(* Logix 5000 project; controller PDPMV1_60_v16 vendor 1 type 14 code 65 rev 16.20; software revision 16.03 *)
// MVI69-PDPMV1

TASK MainTask (continuous, watchdog 500 ms) : MainProgram

MODULES
   Controller : vendor 1 type 14 code 65 (CompactLogixL35Controller 0, rev 16.20)
      LocalENB : 1769-L35E Ethernet Port (CompactLogixL35Ethernet 1, rev 16.3)
      Local : CompactBus (CompactVirtualAdapter 3, rev 16.3, Input RPI 5 ms)
         PDPMV1_60 : 1769-MODULE (Compact 1, rev 1.1, Output RPI 2 ms)
END_MODULES

TYPE PDPMV1_AbortConnection :
STRUCT
   Out : PDPMV1_AbortConnection_out;   // Mailbox Request
   In : PDPMV1_AbortConnection_In;   // Mailbox Response
END_STRUCT
END_TYPE

TYPE PDPMV1_AbortConnection_In :
STRUCT
   C_REF : INT;   // Connection reference that shall be terminated.
   ReasonCode : SINT;   // Indicates the reason for the abort request. Value is user-specific. Range 0...15
   Subnet : SINT;   // This parameter encodes information about the origin of the abort initiator. 0: No 1: Local 2: Remote 3...255: (reserved)
   ExtendedFaultInformation : INT;   // If ‘Fault Information’ equals 000Ah or 000Bh, additional information of the error can be found here. For more information,
   FaultInformation : INT;   // If ‘Invalid Other’ is returned in the Message Information word in the header of the response,
END_STRUCT
END_TYPE

TYPE PDPMV1_AbortConnection_out :
STRUCT
   C_REF : INT;   // Connection reference that shall be terminated
   ReasonCode : SINT;   // Indicates the reason for the abort request. Value is user-specific. Range 0...15.
   Subnet : SINT;   // This parameter encodes information about the origin of the abort initiator. 0: No 1: Local 2: Remote
END_STRUCT
END_TYPE

TYPE PDPMV1_Alarm :   // DPV1 alarm data received by the module
STRUCT
   ByteCount : INT;   // Byte count data block
   SlotNumber : SINT;   // Used in the slave to address the desired data block. Range 0-254
   SlaveAddress : SINT;   // Destination of slave (1-125)
   AlarmSpecAck : SINT;   // Additional alarm information
   SeqNumber : SINT;   // Unique ID number of the alarm. Range 0-31.
   ExtDiag : SINT;   // Extended Diagnostic Flag (FFh - flag set and 00h - flag cleared).
   AlarmType : SINT;   // Identifies alarm type. Range is from 1 to 6, 32 to 126.
   FaultInformation : SINT;   // If other than 0, refer to user manual for code information
   Data : SINT[500];   // Returned data [1...n] array with additional manf. spec alarm info.
END_STRUCT
END_TYPE

TYPE PDPMV1_backplane :   // This object stores variables used by the sample ladder for handshaking.
STRUCT
   Read : INT;   // Backplane read statistics
   Write : INT;   // Backplane write statistics
   Error : INT;   // Backplane error statistics
   LastRead : INT;   // Last read block index received from the module
   LastWrite : INT;   // Last write block index received from the module
   BlockIndex : INT;   // Block index of each copy of PROFIBUS input and output blocks
END_STRUCT
END_TYPE

TYPE PDPMV1_backplane2 :   // This object stores variables used by the sample ladder for handshaking.
STRUCT
   LastRead : INT;   // Last read block index received from the module
   LastWrite : INT;   // Last write block index received from the module
   BlockIndex : INT;   // Block index of each copy of PROFIBUS input and output blocks
END_STRUCT
END_TYPE

TYPE PDPMV1_Class1AcyclicRead :   // DPV1 acyclic read mailbox data structure
STRUCT
   Out : PDPMV1_Class1AcyclicRead_Out;   // Mailbox request
   In : PDPMV1_Class1AcyclicRead_In;   // Mailbox response
END_STRUCT
END_TYPE

TYPE PDPMV1_Class1AcyclicRead_In :   // DPV1 acyclic read mailbox response
STRUCT
   ByteCount : INT;   // Byte count data block
   SlotNumber : SINT;   // Used in the slave to address the desired data block.
   SlaveAddress : SINT;   // Destination of slave (1-125)
   Length : SINT;   // Specifies the number of bytes of the data block to read
   Index : SINT;   // Index block
   ErrorDecode : SINT;   // If other than 0, refer to user manual for code information
   ErrorCode2 : SINT;   // If other than 0, refer to user manual for code information
   ErrorCode1 : SINT;   // If other than 0, refer to user manual for code information
   ExtendedFaultInfo : SINT;   // If other than 0, refer to user manual for code information
   FaultInformation : SINT;   // If other than 0, refer to user manual for code information
   Data : SINT[300];   // Returned data [1...n] array
END_STRUCT
END_TYPE

TYPE PDPMV1_Class1AcyclicRead_Out :   // DPV1 acyclic read mailbox request
STRUCT
   SlotNumber : SINT;   // Used in the slave to address the desired data block.
   SlaveAddress : SINT;   // Destination of slave (1-125)
   DataSize : INT;   // Object data size
   Length : SINT;   // Specifies the number of bytes of the data block to read
   Index : SINT;   // Index block
END_STRUCT
END_TYPE

TYPE PDPMV1_Class1AcyclicWrite :   // DPV1 acyclic write mailbox data structure
STRUCT
   Out : PDPMV1_Class1AcyclicWrite_Out;   // Mailbox request
   In : PDPMV1_Class1AcyclicWrite_In;   // Mailbox response
END_STRUCT
END_TYPE

TYPE PDPMV1_Class1AcyclicWrite_In :   // DPV1 acyclic write mailbox response
STRUCT
   ByteCount : INT;   // Byte count data block
   SlotNumber : SINT;   // Used in the slave to address the desired data block.
   SlaveAddress : SINT;   // Destination of slave (1-125)
   Length : SINT;   // Specifies the number of bytes of the data block to read
   Index : SINT;   // Index block
   ErrorDecode : SINT;   // If other than 0, refer to user manual for code information
   ErrorCode2 : SINT;   // If other than 0, refer to user manual for code information
   ErrorCode1 : SINT;   // If other than 0, refer to user manual for code information
   ExtendedFaultInfo : INT;   // If other than 0, refer to user manual for code information
   FaultInformation : INT;   // If other than 0, refer to user manual for code information
   Data : SINT[300];   // Returned data [1...n] array
END_STRUCT
END_TYPE

TYPE PDPMV1_Class1AcyclicWrite_Out :   // DPV1 acyclic write mailbox request
STRUCT
   SlotNumber : SINT;   // Used in the slave to address the desired data block.
   SlaveAddress : SINT;   // Destination of slave (1-125)
   DataSize : INT;   // Object data size
   Length : SINT;   // Specifies the number of bytes of the data block to read
   Index : SINT;   // Index Block
   Data : SINT[300];   // Data that should be written [1...n]
END_STRUCT
END_TYPE

TYPE PDPMV1_Class2AcyclicRead :
STRUCT
   Out : PDPMV1_Class2AcyclicRead_Out;   // Mailbox request
   In : PDPMV1_Class2AcyclicRead_In;   // Mailbox response
END_STRUCT
END_TYPE

TYPE PDPMV1_Class2AcyclicRead_In :
STRUCT
   DataSize : INT;   // Byte count data block
   C_REF : INT;   // Connections references used to identify the connection later on. Range: 1-128
   Index : SINT;   // Index block
   SlotNumber : SINT;   // Used in the slave to address the desired data block.
   Length : INT;   // Specifies the number of bytes of the data block to read
   ErrorDecode : INT;   // If other than 0, refer to user manual for code information
   ErrorCode2 : SINT;   // If other than 0, refer to user manual for code information
   ErrorCode1 : SINT;   // If other than 0, refer to user manual for code information
   ExtendedFaultInfo : SINT;   // If other than 0, refer to user manual for code information
   FaultInformation : SINT;   // If other than 0, refer to user manual for code information
   Data : SINT[244];   // Returned data [1...n] array
END_STRUCT
END_TYPE

TYPE PDPMV1_Class2AcyclicRead_Out :
STRUCT
   C_REF : INT;   // Connection reference that shall be terminated
   Index : SINT;   // Used in the slave for addressing of the desired data block. Range 0...254
   SlotNumber : SINT;   // Used in the slave for addressing of the desired data block. Range 0...254
   Length : INT;   // Number of bytes to write
END_STRUCT
END_TYPE

TYPE PDPMV1_Class2AcyclicWrite :   // DPV1 acyclic write mailbox data structure
STRUCT
   Out : PDPMV1_Class2AcyclicWrite_Out;   // Mailbox request
   In : PDPMV1_Class2AcyclicWrite_In;   // Mailbox response
END_STRUCT
END_TYPE

TYPE PDPMV1_Class2AcyclicWrite_In :   // DPV1 acyclic write mailbox response
STRUCT
   ByteCount : INT;   // Byte count data block
   C_REF : INT;   // Connection reference that shall be Read
   Index : SINT;   // Index block
   SlotNumber : SINT;   // Used in the slave to address the desired data block.
   Length : SINT;   // Specifies the number of bytes of the data block to read
   ErrorDecode : SINT;   // If other than 0, refer to user manual for code information
   ErrorCode2 : SINT;   // If other than 0, refer to user manual for code information
   ErrorCode1 : SINT;   // If other than 0, refer to user manual for code information
   ExtendedFaultInfo : SINT;   // If other than 0, refer to user manual for code information
   FaultInformation : SINT;   // If other than 0, refer to user manual for code information
   Data : SINT[244];   // Returned data [1...n] array
END_STRUCT
END_TYPE

TYPE PDPMV1_Class2AcyclicWrite_Out :   // DPV1 acyclic write mailbox request
STRUCT
   DataSize : INT;   // Object data size
   C_REF : INT;   // Connection reference that shall be terminated
   Index : SINT;   // Index block
   SlotNumber : SINT;   // Used in the slave to address the desired data block.
   Length : INT;   // Specifies the number of bytes of the data block to read
   Data : SINT[244];   // Data that should be written [1...n]
END_STRUCT
END_TYPE

TYPE PDPMV1_Command :   // This object contains the command bits that request mailbox messages from the module.
STRUCT
   StopMode : BOOL;   // Set the module to stop mode (PROFIBUS communication is interrupted in stop mode)
   OperateMode : BOOL;   // Set the module to operate mode (module only communicates through PROFIBUS)
   ClearMode : BOOL;   // Set the module to clear mode (outputs are disabled)
   SynchCRC : BOOL;   // CRC synchronization
   GetLiveList : BOOL;   // Request the Live List information from the module
   GetSlaveConfig : BOOL;   // Request configuration information from slave
   SetSlaveMode : BOOL;   // Set the module to stop mode (PROFIBUS communication is interrupted in stop mode)
   GetSlaveDiagnostics : BOOL;   // Requests slave diagnostics from a slave
   SetSlaveAddress : BOOL;   // Change the slave's PROFIBUS address 100 (only if slave supports this feature)
   StartSlaves : BOOL;   // Restarts PROFIBUS communication with one or more slaves after a "StopSlave" mailbox
   StopSlaves : BOOL;   // Stop PROFIBUS communication with one or more slaves
   Class1AcyclicRead : BOOL;   // Request the module to send acyclic read message to slave
   Class1AcyclicWrite : BOOL;   // Request the module to send acyclic write message to the slave
   InitiateConnection : BOOL;   // Request to establish connection with a V1 slave that can handle class 2 messages
   AbortConnection : BOOL;   // Request to Abort an already established connection with a V1 slave that can handle class 2 messages
   Class2AcyclicRead : BOOL;   // Request the module to send class 2 acyclic Read message to a V1 slave
   Class2AcyclicWrite : BOOL;   // Request the module to send class 2 acyclic Write message to a V1 slave
END_STRUCT
END_TYPE

TYPE PDPMV1_Control :   // Control status
STRUCT
   serial_number : SINT[4];   // Module serial number
   version_MSB : SINT;   // Module version number (most significant byte)
   version_LSB : SINT;   // Module version number (least significant byte)
   mod_status_MSB : SINT;   // Module status (most significant byte)
   mod_status_LSB : SINT;   // Module status (least significant byte)
END_STRUCT
END_TYPE

TYPE PDPMV1_ControlCommand :   // Option bits for SetSlaveMode mailbox
STRUCT
   Reserved1 : BOOL;   // Reserved
   Reserved2 : BOOL;   // Reserved
   Unfreeze_Input : BOOL;   // Freeze mode is concluded when initiated
   Freeze_Input : BOOL;   // Causes the addressed slave to assume freeze mode.
   Unsynchronize_Output : BOOL;   // Unsynchronized output data
   Synchronize_Output : BOOL;   // Synchronized output data
   Reserved3 : BOOL[32];   // Reserved
END_STRUCT
END_TYPE

TYPE PDPMV1_CRC :   // This object stores CRC values for both Profibus and the module.
STRUCT
   ProfibusCRC : DINT;   // Stores Profibus CRC32 values
   ModuleCRC : DINT;   // Stores Module CRC32 values
END_STRUCT
END_TYPE

TYPE PDPMV1_CRC_Struct :   // Module CRC structures
STRUCT
   In : PDPMV1_CRC;   // Mailbox response
   Out : PDPMV1_CRC;   // Mailbox request
END_STRUCT
END_TYPE

TYPE PDPMV1_Fieldbus :   // Fieldbus status
STRUCT
   FB_Slave_Cfg_List : SINT[16];   // Bitmap structure containing PROFIBUS slave configuration (bit x = 1 means slave x is configured)
   FB_Slave_Data_xfer : SINT[16];   // Bitmap structure containing PROFIBUS slave data exchange status (bit x = 1 means slave x is transferring data to the module)
   FB_Slave_Diag : SINT[16];   // Bitmap structure containing PROFIBUS slave diagnostic info (bit x = 1 means slave x is reporting diagnostics)
   FB_Pad_Byte : SINT;   // Reserved
   FB_op_state : SINT;   // Operation state ( 00 = offline, 40 = stop, 80 = clear, C0= operate)
   FB_ident_MSB : SINT;   // Master identification code (most significant byte)
   FB_ident_LSB : SINT;   // Master identification code (least significant byte)
END_STRUCT
END_TYPE

TYPE PDPMV1_GetLiveList :   // GetLiveList mailbox to retrieve the live list information from PROFIBUS network, informing the slaves that are communicating
STRUCT
   ReturnCode : SINT;   // Returned code about the nodes on the network
   FaultInfo : SINT;   // If other than 0, refer to user manual for code information
   Station : SINT[127];   // Station type contents.
END_STRUCT
END_TYPE

TYPE PDPMV1_GetSlaveConfig :   // GetSlaveConfig mailobox to retrieve configuration data from specific PROFIBUS slaves
STRUCT
   Out : PDPMV1_GetSlaveConfig_Out;   // mailbox request
   In : PDPMV1_GetSlaveConfig_In;   // mailbox response
END_STRUCT
END_TYPE

TYPE PDPMV1_GetSlaveConfig_In :   // GetSlaveConfig mailbox response
STRUCT
   ByteCount : INT;   // Byte count data block
   WordCount : INT;   // Word count data block
   SlaveAddress : INT;   // Destination of slave (1-125)
   ErrorCode : INT[1];   // If other than 0, refer to user manual for code information
   ReturnCode : INT;   // If other than 0, refer to user manual for code information
   FaultInformation : INT;   // If other than 0, refer to user manual for code information
   Identifier : SINT[245];   // Configuration from a specific connected PROFIBUS slave
END_STRUCT
END_TYPE

TYPE PDPMV1_GetSlaveConfig_Out :   // GetSlaveConfig mailbox request
STRUCT
   SlaveAddress : INT;   // Destination of slave (1-125)
END_STRUCT
END_TYPE

TYPE PDPMV1_GetSlaveDiagnostics :   // GetSlaveDiagnostics mailbox to retrieve diagnostic information from specific PROFIBUS slaves
STRUCT
   Out : PDPMV1_GetSlaveDiagnostics_Out;   // Mailbox request
   In : PDPMV1_GetSlaveDiagnostics_In;   // Mailbox response
END_STRUCT
END_TYPE

TYPE PDPMV1_GetSlaveDiagnostics_In :   // GetSlaveDiagnostics mailbox response
STRUCT
   RequestType : SINT;   // Type of request. 0 to use module memory RAM or 1 for live PROFIBUS network.
   SlaveAddress : SINT;   // Destination of slave (Range 1-125)
   ExtendedFaultInfo : INT;   // If other than 0, refer to user manual for code information
   FaultInformation : INT;   // If other than 0, refer to user manual for code information
   StationStatus1_2 : INT;   // Status of station types 1 and 2
   StationStatus3_4 : INT;   // Status of station types 3 and 4
   IdentNumber : INT;   // Unique ID assigned by the PROFIBUS User Organization
   ExtendedDiagnosticData : INT[200];   // Slave user-specific data. Refer to actual slave documentation for info
END_STRUCT
END_TYPE

TYPE PDPMV1_GetSlaveDiagnostics_Out :   // GetSlaveDiagnostics mailbox request
STRUCT
   RequestType : SINT;   // Type of request. 0 to use module memory RAM or 1 for live PROFIBUS network.
   SlaveAddress : SINT;   // Destination of slave (Range 1-125)
END_STRUCT
END_TYPE

TYPE PDPMV1_InitiateConnection :
STRUCT
   Out : PDPMV1_InitiateConnection_out;   // Mailbox Request
   In : PDPMV1_InitiateConnection_In;   // Mailbox response
END_STRUCT
END_TYPE

TYPE PDPMV1_InitiateConnection_In :   // This tag holds the response parameters after the user sends mailbox to initiate connection with V1 slave
STRUCT
   SizeofdatainBytes : INT;   // Size of data being read
   C_REF : INT;   // Connections references used to identify the connection later on. Range: 1-128
   MaxDataLength : SINT;   // The slave’s maximum data length in bytes (reported by the slave in DP Initiate.res).
   SlaveAddress : SINT;   // Address of the slave to which a connection shall be established. Range: 0...126
   MinmumSlaveTimeout : INT;   // The minimum slave timeout value supported by the slave (in multiples of 10ms).
   ErrorDecode : SINT;   // If ‘Fault Information’ equals 0010h, additional information according to the DPV1 specification
   ErrorCode2 : SINT;   // If ‘Fault Information’ equals 0010h, additional information according to the DPV1 specification
   ErrorCode1 : SINT;   // If ‘Fault Information’ equals 0010h, additional information according to the DPV1 specification
   ExtendedFaultInformation : INT;   // If ‘Fault Information’ equals 000Ah or 000Bh, additional information of the error can be found here. For more information, see
   FaultInformation : INT;   // If ‘Invalid Other’ is returned in the Message Information word in the header of the response, information about the fault
   SendTimeout : INT;   // Defines the control time (timebase 10ms) for the supervision of the connection between the slave and the master. Range 6...655
   FeatureSupported2 : SINT;   // (reserved for future use)
   FeatureSupported1 : SINT;   // Identifies the supported C2-service functionality as follows: b0: DPV1_RW. This bit is set if the services C2_Read and C2_Write
   ProfileFeatures2 : SINT;   // Identifies the supported service functionality regarding the used profile definition. The meaning of these registers are profil
   ProfileFeatures1 : SINT;   // Identifies the supported service functionality regarding the used profile definition. The meaning of these registers are profil
   ProfileIdentNumber : INT;   // This parameter identifies a unique profile definition. The Profile Ident Number is taken from the pool of Ident Numbers managed
   S_Length : SINT;   // This parameter specifies the length of the S_Address parameter (see table below). Default value is 02h.
   S_Type : SINT;   // This parameter indicates the presence of the optional Network/MAC address of the source. b0: 1: A Network/MAC address is presen
   D_Length : SINT;   // This value specifies the length of the D_Address parameter (see table below). Default value is 02h.
   D_Type : SINT;   // This parameter indicates the presence of the optional Network/MAC address of the destination. b0: 1: A Network/MAC address is p
   S_Address : INT;   // This field holds additional address information about the source. It’s structure depends on the settings in S_Type.
   D_Address : INT;   // This field holds additional address information about the destination. It’s structure depends on the settings in D_Type
END_STRUCT
END_TYPE

TYPE PDPMV1_InitiateConnection_out :
STRUCT
   SlaveAddress : INT;   // Address of the slave to which a connection shall be established. Range: 0...126
   C_REF : INT;   // Connections references used to identify the connection later on. Range: 1-128
END_STRUCT
END_TYPE

TYPE PDPMV1_Mailbox :   // Stores all mailbox request and response registers
STRUCT
   GetLiveList : PDPMV1_GetLiveList;   // Gets information from all nodes on the network
   GetSlaveConfig : PDPMV1_GetSlaveConfig;   // Get slave configuration
   SetSlaveMode : PDPMV1_SetSlaveMode;   // Send special control command to one or several slaves (Sync/Freeze)
   GetSlaveDiagnostics : PDPMV1_GetSlaveDiagnostics;   // Get diagnostic information from a slave
   SetSlaveAddress : PDPMV1_SetSlaveAddress;   // Set node address of a slave (if supported by the slave)
   StartStopSlaves : PDPMV1_Start_Stop_Slaves;   // Start/Stop slaves dynamically
   Class1AcyclicRead : PDPMV1_Class1AcyclicRead;   // Initiates a DPV1 class 1 acyclic read request.
   Class1AcyclicWrite : PDPMV1_Class1AcyclicWrite;   // Initiates a DPV1 class 1 acyclic write request.
   Alarm : PDPMV1_Alarm;   // Alarm message transferred by a slave to the master
   InitiateConnection : PDPMV1_InitiateConnection;   // mailbox form used to initiate connection with v1 slave before sending class2 messages.
   AbortConnection : PDPMV1_AbortConnection;   // mailbox form used to abort an already established connection with v1 slave before sending class2 messages.
   Class2AcyclicRead : PDPMV1_Class2AcyclicRead;   // mailbox form used to send a class 2 messages to read acyclic data
   Class2AcyclicWrite : PDPMV1_Class2AcyclicWrite;   // mailbox form used to send a class 2 messages to write acyclic data
END_STRUCT
END_TYPE

TYPE PDPMV1_MBControl :   // PDPMV1 Mailbox Control status.
STRUCT
   Out_MB_index : INT;   // Reserved
   In_MB_index : INT;   // Reserved
   Alarm_MB_index : INT;   // Reserved
   In_Last_Out_MB : INT;   // Last out mailbox message ID processed from output image
   In_Last_In_MB : INT;   // Current in mailbox control index
   In_Last_Alarm_MB : INT;   // Current alarm control index
   Out_Last_Out_MB : INT;   // Reserved
   Out_Last_In_MB : INT;   // Reserved
   Out_Last_Alarm_MB : INT;   // Reserved
END_STRUCT
END_TYPE

TYPE PDPMV1_Module :   // Status data
STRUCT
   Mod_scan_count : INT;   // Incremented every module scan loop
   Mod_output_update : INT;   // Incremented at every output scan
   Mod_input_update : INT;   // Incremented at every input scan
   Mod_out_MB : INT;   // Incremented at every output mailbox processing
   Mod_in_MB : INT;   // Incremented at every intput mailbox processing
   Mod_alarm_ind : INT;   // Incremented at every alarm indication
   Mod_alarm_con : INT;   // Incremented at every alarm confirmation
   Reserved1 : INT;   // Reserved
   Reserved2 : INT;   // Reserved
END_STRUCT
END_TYPE

TYPE PDPMV1_ModuleDef :   // Main module definition
STRUCT
   Output : SINT[1536];   // Output data
   Input : SINT[1536];   // Input data
   BP : PDPMV1_backplane2;   // Backplane status
   Status : PDPMV1_Status;   // Module status information
   MailboxCommand : PDPMV1_Command;   // Mailbox Command
   Mailbox : PDPMV1_Mailbox;   // Mailbox tags for optional applications
   CRC : PDPMV1_CRC_Struct;   // CRC status
   MailboxControl : PDPMV1_MBControl;   // Mailbox Control
   Util : PDPMV1_Util;   // Internal tags used for ladder logic processing. User applications should not overwrite any Util tags
END_STRUCT
END_TYPE

TYPE PDPMV1_other_status :   // This object contains specific information, such as the number of mailbox and alarms located in the mailbox queue.
STRUCT
   Cfg_file_error : INT;   // Bit0 = PDPMV1.CFG, Bit 1 = WATTCP.CFG, Bit 2 = PDPMV1.DDB, Bit3=PDPMV1.XML
   R_120 : INT;   // Not Used
   R_122 : INT;   // Not Used
   R_124 : INT;   // Not Used
   R_126 : INT;   // Not Used
   R_128 : INT;   // Not Used
   R_130 : INT;   // Not Used
   R_132 : INT;   // Not Used
   R_134 : INT;   // Not Used
   R_136 : INT;   // Not Used
   R_138 : INT;   // Not Used
   R_140 : INT;   // Not Used
   R_142 : INT;   // Not Used
   R_144 : INT;   // Not Used
   In_MB_queue : INT;   // Number of messages in the input mailbox queue
   Out_MB_queue : INT;   // Number of messages in the output mailbox queue
   Alarm_MB_queue : INT;   // Number of messages in the alarm mailbox queue
   Last_out_MB : INT;   // Number of messages in the output mailbox queue
   Cur_in_MB : INT;   // Number of messages currently in the input mailbox queue
   Cur_alarm_MB : INT;   // Number of messages currently in the alarm mailbox queue
END_STRUCT
END_TYPE

TYPE PDPMV1_SetSlaveAddress :   // SetSlaveAddress mailbox that allows the module to dynamically change a PRIDUBUS address (only for slaves that supports it)
STRUCT
   Out : PDPMV1_SetSlaveAddress_Out;   // Mailbox request
   In : PDPMV1_SetSlaveAddress_In;   // Mailbox response
END_STRUCT
END_TYPE

TYPE PDPMV1_SetSlaveAddress_In :   // Mailbox response
STRUCT
   ByteCount : INT;   // Byte count data block
   NewSlaveAddress : SINT;   // Range 1 to 125, specifies the new address of the slave
   CurrentSlaveAddress : SINT;   // Range 1 to 125, specifies the current address of the slave
   SlaveIdentNumber : INT;   // Indent number for the slave
   No_add_Chg : INT;   // specifies whether it is allowed to change the slave address again later
   ErrorCode1_2 : INT;   // If other than 0, refer to user manual for code information
   ErrorCode3_4 : INT;   // If other than 0, refer to user manual for code information
   ReturnCode : INT;   // If other than 0, refer to user manual for code information
   FaultInformation : INT;   // If other than 0, refer to user manual for code information
   MessageDataByte : SINT[400];   // Message data byte array for user-specific data
END_STRUCT
END_TYPE

TYPE PDPMV1_SetSlaveAddress_Out :   // Mailbox request
STRUCT
   ByteCount : INT;   // Byte count data block
   NewSlaveAddress : SINT;   // Range 1 to 125, specifies the new address of the slave
   CurrentSlaveAddress : SINT;   // Range 1 to 125, specifies the current address of the slave
   SlaveIdentNumber : INT;   // Indent number for the slave
   No_add_Chg : INT;   // specifies whether it is allowed to change the slave address again later
   MessageDataByte : SINT[400];   // Message data byte array for user-specific data
END_STRUCT
END_TYPE

TYPE PDPMV1_SetSlaveMode :   // SetSlaveMode mailbox that allows the processor to change the slave mode to interrupt input or output data update
STRUCT
   Out : PDPMV1_SetSlaveMode_Out;   // Mailbox Request
   In : PDPMV1_SetSlaveMode_In;   // Mailbox Response
END_STRUCT
END_TYPE

TYPE PDPMV1_SetSlaveMode_In :   // Mailbox response
STRUCT
   GroupSelect : SINT;   // Range 01h to FFh (Bit Coded). This parameter determines which group to address. Refer to the user manual for examples
   SlaveAddress : SINT;   // Range 1 to 125; 127 (Multicast address).
   ControlCommand : PDPMV1_ControlCommand;   // This parameter specifies the command to send (Unsync/Sync and Unfreeze/Freeze).
   ExtendedFaultInfo : INT;   // If other than 0, refer to user manual for code information
   FaultInformation : INT;   // If other than 0, refer to user manual for code information
END_STRUCT
END_TYPE

TYPE PDPMV1_SetSlaveMode_Out :   // Mailbox Request
STRUCT
   GroupSelect : SINT;   // Range 01h to FFh (Bit Coded). This parameter determines which group to address. Refer to the user manual for examples
   SlaveAddress : SINT;   // Range 1 to 125; 127 (Multicast address).
   ControlCommand : PDPMV1_ControlCommand;   // This parameter specifies the command to send (Unsync/Sync and Unfreeze/Freeze).
END_STRUCT
END_TYPE

TYPE PDPMV1_Start_Stop_Slaves :   // Start/Stop Slaves mailbox allows the processor to restart or hault slave communication.
STRUCT
   Out : PDPMV1_Start_Stop_Slaves_Out;   // Mailbox Request
   In : PDPMV1_Start_Stop_Slaves_In;   // Mailbox Response
END_STRUCT
END_TYPE

TYPE PDPMV1_Start_Stop_Slaves_In :   // Mailbox response
STRUCT
   AdditionalFaultInfo : INT;   // If other than 0, refer to user manual for code information
   FaultInformation : INT;   // If other than 0, refer to user manual for code information
   SlaveNumber : SINT[126];   // Slave number designation (Range 1-125)
END_STRUCT
END_TYPE

TYPE PDPMV1_Start_Stop_Slaves_Out :   // Mailbox request
STRUCT
   SlaveNumber : SINT[126];   // Slave number designation (1-125)
END_STRUCT
END_TYPE

TYPE PDPMV1_Status :   // Status block 0 or -1 for the MVI56-PDPMV1 module
STRUCT
   Pattern : SINT[12];   // Module indentification code
   Input_Size : INT;   // Input data size
   Output_Size : INT;   // Output data size
   Reserved_16 : INT;   // Reserved
   Reserved_18 : INT;   // Reserved
   Reserved_20 : INT;   // Reserved
   Input_Swap : SINT;   // User configured flag to indicate if input data is swapped before placing in the input image of the controller
   Output_Swap : SINT;   // User configured flag to indicate if output data is swapped before placing in the output image of the controller
   Module_Major_Ver : SINT;   // Module software major version number
   Module_Minor_Ver : SINT;   // Module software minor version number
   Fieldbus : PDPMV1_Fieldbus;   // PROFIBUS network status information
   Control : PDPMV1_Control;   // Module information
   Profibus_CRC32 : DINT;   // Profibus CRC32 value
   Module_CRC32 : DINT;   // Module CRC32 value
   Module : PDPMV1_Module;   // General module status to monitor data, mailbox and alarm exchange between the processor and the module
   Backplane : PDPMV1_backplane;   // Backplane status information
   Other : PDPMV1_other_status;   // General mailbox and cfg error information
END_STRUCT
END_TYPE

TYPE PDPMV1_Util :
STRUCT
   ByteSwapUtil : INT;   // Used for byte swap logic
   TempInt : INT;   // Used for integer formatting
   UtilCount : INT;   // Used for util count range
   Finishmailboxreading : BOOL;   // Used to finish mailbox requests and response reading
   TempInt2 : INT;   // Used to copy value to it then use it for comparison
   SetSlaveAddress101 : BOOL;   // Change the slave's PROFIBUS address 101 (only if slave supports this feature)
   SetSlaveAddress102 : BOOL;   // Change the slave's PROFIBUS address 102 (only if slave supports this feature)
   Class1AcyclicWrite101 : BOOL;   // Request the module to send acyclic write message to the slave
   Class1AcyclicWrite102 : BOOL;   // Request the module to send acyclic write message to the slave
   Class2AcyclicWrite101 : BOOL;   // Request the module to send Class2 acyclic write message to slave 101
   Class2AcyclicWrite102 : BOOL;   // Request the module to send Class2 acyclic write message to slave 102
   Finishgetlivelist : BOOL;   // Finish requesting the Live List information from the module
   FinishgetSlaveconfig : BOOL;   // Finish requesting configuration information from a slave
   FinishgetSlaveDiagnost : BOOL;   // Finish requesting slave diagnostics from a slave
   FinishSetSlaveAddr : BOOL;   // Finish changing the slaves PROFIBUS addressing
   FinishClass1AcyclicRead : BOOL;   // Finish requesting the module to send acyclic read message to slave
   FinishClass1AcyclicWrite : BOOL;   // Finish requesting the module to send acyclic write message to slave
   FinishStartStopSlaves : BOOL;   // Finish PROFIBUS communications with one or more slaves if supported
   FinishClass2AcyclicRead : BOOL;   // Finish requesting the module to send Class 2 acyclic read message to slave
   FinishClass2AcyclicWrite : BOOL;   // Finish requesting the module to send acyclic write message to slave
END_STRUCT
END_TYPE

ADD_ON_INSTRUCTION AOI69PDPMV1_60   (* revision 1.4 *)
// Add-On - MVI69-PDPMV1(Block size 60).
// Revision note:
// v1.4 - Added support for class 2 messages that was supported in a specific  V1 slaves.
VAR_IN_OUT
   Connection_Input : INT[62]; {required}   // Connection Input to be associated to the MVI69PDPMV1 Input Array
   Connection_Output : INT[61]; {required}   // Connection Output to be associated to the MVI69-PDPMV1 Output Array
   MVI69PDPMV1 : PDPMV1_ModuleDef; {required}
END_VAR

ROUTINE Logic   (* ladder *)
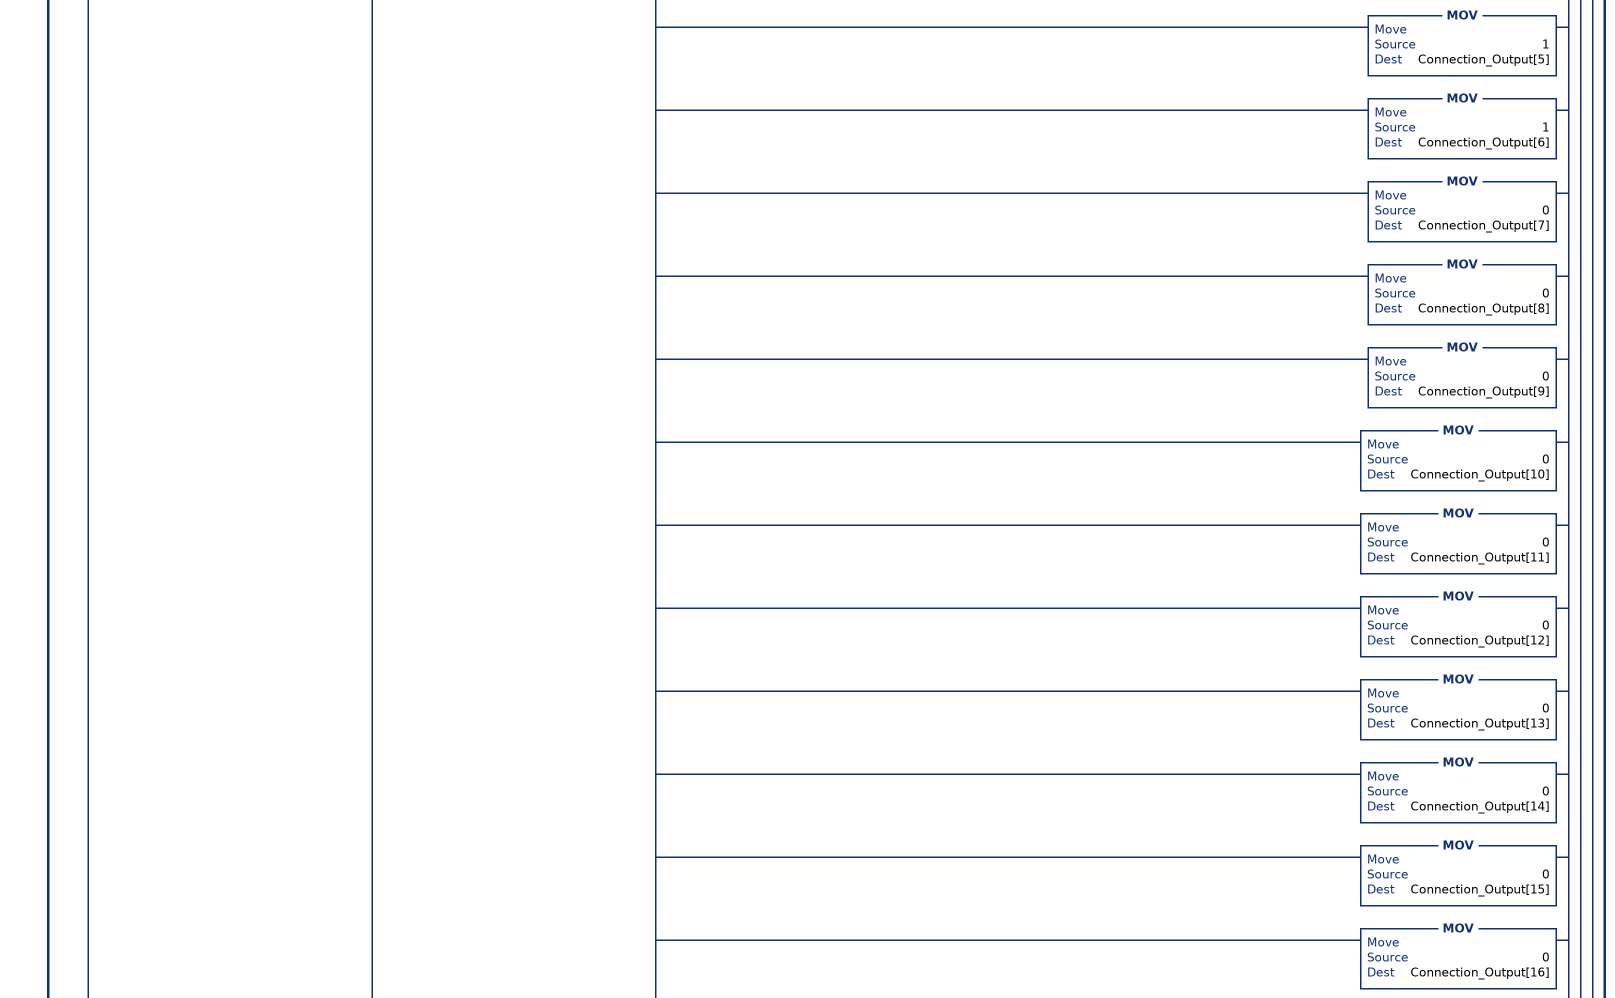
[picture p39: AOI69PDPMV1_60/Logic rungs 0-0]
   // This rung is used to verify if the module has sent a new input block to the processor. The trigger is when the input image offset 0 (Read Block ID) is different than the last one processed by the processor
   0: NEQ(Connection_Input[0],MVI69PDPMV1.BP.LastRead)[MOV(Connection_Input[0],MVI69PDPMV1.BP.LastRead) ,EQU(MVI69PDPMV1.BP.LastRead,-1) [COP(Connection_Input[2],MVI69PDPMV1.Status.Pattern[0],20) ,COP(Connection_Input[13],MVI69PDPMV1.Status.Input_Swap,4) ,COP(Connection_Input[15],MVI69PDPMV1.Status.Fieldbus.FB_Slave_Cfg_List[0],52) ,COP(Connection_Input[41],MVI69PDPMV1.Status.Control.serial_number[0],8) ,COP(Connection_Input[45],MVI69PDPMV1.Status.Profibus_CRC32,2) ] ,EQU(MVI69PDPMV1.BP.LastRead,0) [COP(Connection_Input[2],MVI69PDPMV1.Status.Module.Mod_scan_count,9) ,COP(Connection_Input[11],MVI69PDPMV1.Status.Backplane.Read,3) ,COP(Connection_Input[14],MVI69PDPMV1.Status.Other.Cfg_file_error,20) ] ,LIM(1,MVI69PDPMV1.BP.LastRead,16) [LIM(1,MVI69PDPMV1.BP.LastRead,15) [CPT(MVI69PDPMV1.BP.BlockIndex,(MVI69PDPMV1.BP.LastRead-1)*100) ,COP(Connection_Input[2],MVI69PDPMV1.Input[MVI69PDPMV1.BP.BlockIndex],100) ] ,EQU(MVI69PDPMV1.BP.LastRead,16) COP(Connection_Input[2],MVI69PDPMV1.Input[1500],36) ,COP(Connection_Input[52],MVI69PDPMV1.MailboxControl.In_Last_Out_MB,2) ,COP(Connection_Input[56],MVI69PDPMV1.CRC.In.ProfibusCRC,2) ] ,LIM(100,MVI69PDPMV1.BP.LastRead,102) [EQU(100,MVI69PDPMV1.BP.LastRead) LIM(0,Connection_Input[2],2) [OTU(MVI69PDPMV1.MailboxCommand.StopMode) ,OTU(MVI69PDPMV1.MailboxCommand.OperateMode) ,OTU(MVI69PDPMV1.MailboxCommand.ClearMode) ,OTU(MVI69PDPMV1.MailboxCommand.SetSlaveMode) ] ,XIC(MVI69PDPMV1.Util.Finishgetlivelist) [EQU(Connection_Input[4],24) EQU(100,MVI69PDPMV1.BP.LastRead) [MOV(Connection_Input[5],MVI69PDPMV1.Util.UtilCount) ,COP(Connection_Input[18],MVI69PDPMV1.Mailbox.GetLiveList.Station[0],88) ,LEQ(MVI69PDPMV1.Util.UtilCount,88) OTU(MVI69PDPMV1.Util.Finishgetlivelist) ] ,EQU(101,MVI69PDPMV1.BP.LastRead) [COP(Connection_Input[2],MVI69PDPMV1.Mailbox.GetLiveList.Station[88],39) ,OTU(MVI69PDPMV1.Util.Finishgetlivelist) ] ] ,EQU(Connection_Input[4],3) [COP(Connection_Input[10],MVI69PDPMV1.Mailbox.SetSlaveMode.In.GroupSelect,2) ,MOV(Connection_Input[11],MVI69PDPMV1.Util.TempInt) ,SWPB(MVI69PDPMV1.Util.TempInt,REVERSE,MVI69PDPMV1.Util.ByteSwapUtil) ,COP(MVI69PDPMV1.Util.ByteSwapUtil,MVI69PDPMV1.Mailbox.SetSlaveMode.In.ControlCommand,1) ,MOV(Connection_Input[16],MVI69PDPMV1.Mailbox.SetSlaveMode.In.ExtendedFaultInfo) ,MOV(Connection_Input[17],MVI69PDPMV1.Mailbox.SetSlaveMode.In.FaultInformation) ] ,XIC(MVI69PDPMV1.Util.FinishgetSlaveDiagnost) [EQU(100,MVI69PDPMV1.BP.LastRead) EQU(Connection_Input[4],4) [MOV(Connection_Input[5],MVI69PDPMV1.Util.UtilCount) ,COP(Connection_Input[10],MVI69PDPMV1.Mailbox.GetSlaveDiagnostics.In.RequestType,2) ,MOV(Connection_Input[16],MVI69PDPMV1.Mailbox.GetSlaveDiagnostics.In.ExtendedFaultInfo) ,MOV(Connection_Input[17],MVI69PDPMV1.Mailbox.GetSlaveDiagnostics.In.FaultInformation) ,MOV(Connection_Input[18],MVI69PDPMV1.Mailbox.GetSlaveDiagnostics.In.StationStatus1_2) ,MOV(Connection_Input[19],MVI69PDPMV1.Mailbox.GetSlaveDiagnostics.In.StationStatus3_4) ,MOV(Connection_Input[20],MVI69PDPMV1.Mailbox.GetSlaveDiagnostics.In.IdentNumber) ,COP(Connection_Input[21],MVI69PDPMV1.Mailbox.GetSlaveDiagnostics.In.ExtendedDiagnosticData[0],41) ,LEQ(MVI69PDPMV1.Util.UtilCount,41) OTU(MVI69PDPMV1.Util.FinishgetSlaveDiagnost) ] ,EQU(101,MVI69PDPMV1.BP.LastRead) [SUB(MVI69PDPMV1.Util.UtilCount,41,MVI69PDPMV1.Util.UtilCount) ,COP(Connection_Input[2],MVI69PDPMV1.Mailbox.GetSlaveDiagnostics.In.ExtendedDiagnosticData[41],60) ,LEQ(MVI69PDPMV1.Util.UtilCount,60) OTU(MVI69PDPMV1.Util.FinishgetSlaveDiagnost) ] ,EQU(102,MVI69PDPMV1.BP.LastRead) [COP(Connection_Input[2],MVI69PDPMV1.Mailbox.GetSlaveDiagnostics.In.ExtendedDiagnosticData[101],24) ,OTU(MVI69PDPMV1.Util.FinishgetSlaveDiagnost) ] ] ,XIC(MVI69PDPMV1.Util.FinishgetSlaveconfig) [EQU(MVI69PDPMV1.BP.LastRead,100) EQU(Connection_Input[4],5) [MOV(Connection_Input[5],MVI69PDPMV1.Mailbox.GetSlaveConfig.In.ByteCount) ,MOV(Connection_Input[10],MVI69PDPMV1.Util.ByteSwapUtil) ,SWPB(MVI69PDPMV1.Util.ByteSwapUtil,REVERSE,MVI69PDPMV1.Mailbox.GetSlaveConfig.In.SlaveAddress) ,COP(Connection_Input[14],MVI69PDPMV1.Mailbox.GetSlaveConfig.In.ErrorCode[0],2) ,MOV(Connection_Input[16],MVI69PDPMV1.Mailbox.GetSlaveConfig.In.ReturnCode) ,MOV(Connection_Input[17],MVI69PDPMV1.Mailbox.GetSlaveConfig.In.FaultInformation) ,COP(Connection_Input[18],MVI69PDPMV1.Mailbox.GetSlaveConfig.In.Identifier[0],88) ,LEQ(MVI69PDPMV1.Mailbox.GetSlaveConfig.In.ByteCount,88) OTU(MVI69PDPMV1.Util.FinishgetSlaveconfig) ] ,EQU(MVI69PDPMV1.BP.LastRead,101) [SUB(MVI69PDPMV1.Mailbox.GetSlaveConfig.In.ByteCount,88,MVI69PDPMV1.Mailbox.GetSlaveConfig.In.ByteCount) ,COP(Connection_Input[2],MVI69PDPMV1.Mailbox.GetSlaveConfig.In.Identifier[88],120) ,LEQ(MVI69PDPMV1.Mailbox.GetSlaveConfig.In.ByteCount,120) OTU(MVI69PDPMV1.Util.FinishgetSlaveconfig) ] ,EQU(MVI69PDPMV1.BP.LastRead,102) [COP(Connection_Input[2],MVI69PDPMV1.Mailbox.GetSlaveConfig.In.Identifier[208],48) ,OTU(MVI69PDPMV1.Util.FinishgetSlaveconfig) ] ] ,XIC(MVI69PDPMV1.Util.FinishSetSlaveAddr) [EQU(Connection_Input[4],6) EQU(MVI69PDPMV1.BP.LastRead,100) [MOV(Connection_Input[5],MVI69PDPMV1.Mailbox.SetSlaveAddress.In.ByteCount) ,COP(Connection_Input[10],MVI69PDPMV1.Mailbox.SetSlaveAddress.In.NewSlaveAddress,2) ,MOV(Connection_Input[11],MVI69PDPMV1.Mailbox.SetSlaveAddress.In.SlaveIdentNumber) ,MOV(Connection_Input[12],MVI69PDPMV1.Util.ByteSwapUtil) ,SWPB(MVI69PDPMV1.Util.ByteSwapUtil,REVERSE,MVI69PDPMV1.Mailbox.SetSlaveAddress.In.No_add_Chg) ,MOV(Connection_Input[14],MVI69PDPMV1.Mailbox.SetSlaveAddress.In.ErrorCode1_2) ,MOV(Connection_Input[15],MVI69PDPMV1.Mailbox.SetSlaveAddress.In.ErrorCode3_4) ,MOV(Connection_Input[16],MVI69PDPMV1.Mailbox.SetSlaveAddress.In.ReturnCode) ,MOV(Connection_Input[17],MVI69PDPMV1.Mailbox.SetSlaveAddress.In.FaultInformation) ,COP(Connection_Input[18],MVI69PDPMV1.Mailbox.SetSlaveAddress.In.MessageDataByte[0],88) ,LEQ(MVI69PDPMV1.Mailbox.SetSlaveAddress.Out.ByteCount,88) OTU(MVI69PDPMV1.Util.FinishSetSlaveAddr) ,GRT(MVI69PDPMV1.Mailbox.SetSlaveAddress.Out.ByteCount,88) [SUB(88,MVI69PDPMV1.Mailbox.SetSlaveAddress.Out.ByteCount,MVI69PDPMV1.Mailbox.SetSlaveAddress.Out.ByteCount) ,OTL(MVI69PDPMV1.Util.SetSlaveAddress101) ,OTL(MVI69PDPMV1.Util.Finishmailboxreading) ] ] ,EQU(MVI69PDPMV1.BP.LastRead,101) XIC(MVI69PDPMV1.Util.Finishmailboxreading) [LEQ(MVI69PDPMV1.Mailbox.SetSlaveAddress.Out.ByteCount,120) [COP(Connection_Input[2],MVI69PDPMV1.Mailbox.SetSlaveAddress.In.MessageDataByte[88],120) ,OTU(MVI69PDPMV1.Util.Finishmailboxreading) ,OTU(MVI69PDPMV1.Util.SetSlaveAddress101) ,MOV(0,MVI69PDPMV1.Mailbox.SetSlaveAddress.Out.ByteCount) ] ,GRT(MVI69PDPMV1.Mailbox.SetSlaveAddress.Out.ByteCount,120) [SUB(120,MVI69PDPMV1.Mailbox.SetSlaveAddress.Out.ByteCount,MVI69PDPMV1.Mailbox.SetSlaveAddress.Out.ByteCount) ,OTL(MVI69PDPMV1.Util.FinishSetSlaveAddr) ,OTL(MVI69PDPMV1.Util.Finishmailboxreading) ] ] ,EQU(MVI69PDPMV1.BP.LastRead,102) [COP(Connection_Input[2],MVI69PDPMV1.Mailbox.SetSlaveAddress.In.MessageDataByte[208],48) ,OTU(MVI69PDPMV1.Util.FinishSetSlaveAddr) ,OTU(MVI69PDPMV1.Util.Finishmailboxreading) ,MOV(0,MVI69PDPMV1.Mailbox.SetSlaveAddress.Out.ByteCount) ] ] ,XIC(MVI69PDPMV1.Util.FinishStartStopSlaves) [LIM(11,Connection_Input[4],12) EQU(MVI69PDPMV1.BP.LastRead,100) [MOV(Connection_Input[16],MVI69PDPMV1.Mailbox.StartStopSlaves.In.AdditionalFaultInfo) ,MOV(Connection_Input[17],MVI69PDPMV1.Mailbox.StartStopSlaves.In.FaultInformation) ,COP(Connection_Input[18],MVI69PDPMV1.Mailbox.StartStopSlaves.In.SlaveNumber[0],88) ] ,EQU(MVI69PDPMV1.BP.LastRead,101) [COP(Connection_Input[2],MVI69PDPMV1.Mailbox.StartStopSlaves.In.SlaveNumber[88],40) ,OTU(MVI69PDPMV1.Util.FinishStartStopSlaves) ] ] ,XIC(MVI69PDPMV1.Util.FinishClass1AcyclicRead) [EQU(100,MVI69PDPMV1.BP.LastRead) EQU(Connection_Input[4],32) [MOV(Connection_Input[5],MVI69PDPMV1.Mailbox.Class1AcyclicRead.In.ByteCount) ,COP(Connection_Input[10],MVI69PDPMV1.Mailbox.Class1AcyclicRead.In.SlotNumber,2) ,COP(Connection_Input[11],MVI69PDPMV1.Mailbox.Class1AcyclicRead.In.Length,2) ,COP(Connection_Input[14],MVI69PDPMV1.Mailbox.Class1AcyclicRead.In.ErrorDecode,1) ,COP(Connection_Input[15],MVI69PDPMV1.Mailbox.Class1AcyclicRead.In.ErrorCode2,2) ,MOV(Connection_Input[16],MVI69PDPMV1.Mailbox.Class1AcyclicRead.In.ExtendedFaultInfo) ,MOV(Connection_Input[17],MVI69PDPMV1.Mailbox.Class1AcyclicRead.In.FaultInformation) ,COP(Connection_Input[18],MVI69PDPMV1.Mailbox.Class1AcyclicRead.In.Data[0],88) ,LEQ(MVI69PDPMV1.Mailbox.Class1AcyclicRead.In.ByteCount,88) OTU(MVI69PDPMV1.Util.FinishClass1AcyclicRead) ] ,EQU(101,MVI69PDPMV1.BP.LastRead) [SUB(MVI69PDPMV1.Mailbox.Class1AcyclicRead.In.ByteCount,88,MVI69PDPMV1.Mailbox.Class1AcyclicRead.In.ByteCount) ,COP(Connection_Input[2],MVI69PDPMV1.Mailbox.Class1AcyclicRead.In.Data[88],120) ,LEQ(MVI69PDPMV1.Mailbox.Class1AcyclicRead.In.ByteCount,120) OTU(MVI69PDPMV1.Util.FinishClass1AcyclicRead) ] ,EQU(102,MVI69PDPMV1.BP.LastRead) [COP(Connection_Input[2],MVI69PDPMV1.Mailbox.Class1AcyclicRead.In.Data[208],48) ,OTU(MVI69PDPMV1.Util.FinishClass1AcyclicRead) ] ] ,XIC(MVI69PDPMV1.Util.FinishClass1AcyclicWrite) [EQU(100,MVI69PDPMV1.BP.LastRead) EQU(Connection_Input[4],33) [MOV(Connection_Input[5],MVI69PDPMV1.Mailbox.Class1AcyclicWrite.In.ByteCount) ,COP(Connection_Input[10],MVI69PDPMV1.Mailbox.Class1AcyclicWrite.In.SlotNumber,2) ,COP(Connection_Input[11],MVI69PDPMV1.Mailbox.Class1AcyclicWrite.In.Length,2) ,COP(Connection_Input[14],MVI69PDPMV1.Mailbox.Class1AcyclicWrite.In.ErrorDecode,1) ,COP(Connection_Input[15],MVI69PDPMV1.Mailbox.Class1AcyclicWrite.In.ErrorCode2,2) ,MOV(Connection_Input[16],MVI69PDPMV1.Mailbox.Class1AcyclicWrite.In.ExtendedFaultInfo) ,MOV(Connection_Input[17],MVI69PDPMV1.Mailbox.Class1AcyclicWrite.In.FaultInformation) ,COP(Connection_Input[18],MVI69PDPMV1.Mailbox.Class1AcyclicWrite.In.Data[0],88) ,LEQ(MVI69PDPMV1.Mailbox.Class1AcyclicWrite.In.ByteCount,88) OTU(MVI69PDPMV1.Util.FinishClass1AcyclicWrite) ,GRT(MVI69PDPMV1.Mailbox.Class1AcyclicWrite.In.ByteCount,88) OTL(MVI69PDPMV1.Util.Finishmailboxreading) ] ,EQU(101,MVI69PDPMV1.BP.LastRead) XIC(MVI69PDPMV1.Util.Finishmailboxreading) [LES(MVI69PDPMV1.Mailbox.Class1AcyclicWrite.In.ByteCount,120) [COP(Connection_Input[2],MVI69PDPMV1.Mailbox.Class1AcyclicWrite.In.Data[88],MVI69PDPMV1.Mailbox.Class1AcyclicWrite.In.ByteCount) ,OTU(MVI69PDPMV1.Util.FinishClass1AcyclicWrite) ,OTU(MVI69PDPMV1.Util.Finishmailboxreading) ,OTU(MVI69PDPMV1.Util.Class1AcyclicWrite101) ] ,GRT(MVI69PDPMV1.Mailbox.Class1AcyclicWrite.In.ByteCount,120) OTL(MVI69PDPMV1.Util.Finishmailboxreading) ] ,EQU(102,MVI69PDPMV1.BP.LastRead) XIC(MVI69PDPMV1.Util.Finishmailboxreading) [COP(Connection_Input[2],MVI69PDPMV1.Mailbox.Class1AcyclicWrite.In.Data[208],48) ,OTU(MVI69PDPMV1.Util.FinishClass1AcyclicWrite) ,OTU(MVI69PDPMV1.Util.Finishmailboxreading) ] ] ,EQU(Connection_Input[4],37) [MOV(Connection_Input[5],MVI69PDPMV1.Mailbox.InitiateConnection.In.SizeofdatainBytes) ,MOV(Connection_Input[10],MVI69PDPMV1.Mailbox.InitiateConnection.In.C_REF) ,COP(Connection_Input[11],MVI69PDPMV1.Mailbox.InitiateConnection.In.MaxDataLength,2) ,MOV(Connection_Input[12],MVI69PDPMV1.Mailbox.InitiateConnection.In.MinmumSlaveTimeout) ,COP(Connection_Input[14],MVI69PDPMV1.Mailbox.InitiateConnection.In.ErrorDecode,1) ,COP(Connection_Input[15],MVI69PDPMV1.Mailbox.InitiateConnection.In.ErrorCode2,2) ,MOV(Connection_Input[16],MVI69PDPMV1.Mailbox.InitiateConnection.In.ExtendedFaultInformation) ,MOV(Connection_Input[17],MVI69PDPMV1.Mailbox.InitiateConnection.In.FaultInformation) ,MOV(Connection_Input[18],MVI69PDPMV1.Mailbox.InitiateConnection.In.SendTimeout) ,COP(Connection_Input[19],MVI69PDPMV1.Mailbox.InitiateConnection.In.FeatureSupported2,2) ,COP(Connection_Input[20],MVI69PDPMV1.Mailbox.InitiateConnection.In.ProfileFeatures2,2) ,MOV(Connection_Input[21],MVI69PDPMV1.Mailbox.InitiateConnection.In.ProfileIdentNumber) ,COP(Connection_Input[22],MVI69PDPMV1.Mailbox.InitiateConnection.In.S_Length,2) ,COP(Connection_Input[23],MVI69PDPMV1.Mailbox.InitiateConnection.In.D_Length,2) ,MOV(Connection_Input[24],MVI69PDPMV1.Mailbox.InitiateConnection.In.S_Address) ,MOV(Connection_Input[25],MVI69PDPMV1.Mailbox.InitiateConnection.In.D_Address) ] ,EQU(Connection_Input[4],38) [MOV(Connection_Input[10],MVI69PDPMV1.Mailbox.AbortConnection.In.C_REF) ,COP(Connection_Input[11],MVI69PDPMV1.Mailbox.AbortConnection.In.ReasonCode,2) ,MOV(Connection_Input[16],MVI69PDPMV1.Mailbox.AbortConnection.In.ExtendedFaultInformation) ,MOV(Connection_Input[17],MVI69PDPMV1.Mailbox.AbortConnection.In.FaultInformation) ] ,XIC(MVI69PDPMV1.Util.FinishClass2AcyclicRead) [EQU(100,MVI69PDPMV1.BP.LastRead) EQU(Connection_Input[4],39) [MOV(Connection_Input[5],MVI69PDPMV1.Mailbox.Class2AcyclicRead.In.DataSize) ,MOV(Connection_Input[10],MVI69PDPMV1.Mailbox.Class2AcyclicRead.In.C_REF) ,COP(Connection_Input[11],MVI69PDPMV1.Mailbox.Class2AcyclicRead.In.Index,2) ,COP(Connection_Input[12],MVI69PDPMV1.Mailbox.Class2AcyclicRead.In.Length,2) ,COP(Connection_Input[14],MVI69PDPMV1.Mailbox.Class2AcyclicRead.In.ErrorDecode,1) ,COP(Connection_Input[15],MVI69PDPMV1.Mailbox.Class2AcyclicRead.In.ErrorCode2,2) ,MOV(Connection_Input[16],MVI69PDPMV1.Mailbox.Class2AcyclicRead.In.ExtendedFaultInfo) ,MOV(Connection_Input[17],MVI69PDPMV1.Mailbox.Class2AcyclicRead.In.FaultInformation) ,COP(Connection_Input[18],MVI69PDPMV1.Mailbox.Class2AcyclicRead.In.Data[0],88) ,LEQ(MVI69PDPMV1.Mailbox.Class2AcyclicRead.In.DataSize,88) OTU(MVI69PDPMV1.Util.FinishClass2AcyclicRead) ] ,EQU(101,MVI69PDPMV1.BP.LastRead) [SUB(MVI69PDPMV1.Mailbox.Class2AcyclicRead.In.DataSize,88,MVI69PDPMV1.Mailbox.Class2AcyclicRead.In.DataSize) ,COP(Connection_Input[2],MVI69PDPMV1.Mailbox.Class2AcyclicRead.In.Data[208],120) ,LEQ(MVI69PDPMV1.Mailbox.Class2AcyclicRead.In.DataSize,120) OTU(MVI69PDPMV1.Util.FinishClass2AcyclicRead) ] ,EQU(102,MVI69PDPMV1.BP.LastRead) [COP(Connection_Input[2],MVI69PDPMV1.Mailbox.Class2AcyclicRead.In.Data[208],48) ,OTU(MVI69PDPMV1.Util.FinishClass2AcyclicRead) ] ] ,XIC(MVI69PDPMV1.Util.FinishClass2AcyclicWrite) [EQU(100,MVI69PDPMV1.BP.LastRead) EQU(Connection_Input[4],40) [MOV(Connection_Input[5],MVI69PDPMV1.Mailbox.Class2AcyclicWrite.In.ByteCount) ,MOV(Connection_Input[10],MVI69PDPMV1.Mailbox.Class2AcyclicWrite.In.C_REF) ,COP(Connection_Input[11],MVI69PDPMV1.Mailbox.Class2AcyclicWrite.In.Index,2) ,COP(Connection_Input[12],MVI69PDPMV1.Mailbox.Class2AcyclicWrite.In.Length,1) ,COP(Connection_Input[14],MVI69PDPMV1.Mailbox.Class2AcyclicWrite.In.ErrorDecode,1) ,COP(Connection_Input[15],MVI69PDPMV1.Mailbox.Class2AcyclicWrite.In.ErrorCode2,2) ,MOV(Connection_Input[16],MVI69PDPMV1.Mailbox.Class2AcyclicWrite.In.ExtendedFaultInfo) ,MOV(Connection_Input[17],MVI69PDPMV1.Mailbox.Class2AcyclicWrite.In.FaultInformation) ,COP(Connection_Input[18],MVI69PDPMV1.Mailbox.Class2AcyclicWrite.In.Data[0],88) ,LEQ(MVI69PDPMV1.Mailbox.Class2AcyclicWrite.In.ByteCount,88) OTU(MVI69PDPMV1.Util.FinishClass2AcyclicWrite) ,GRT(MVI69PDPMV1.Mailbox.Class2AcyclicWrite.In.ByteCount,88) OTL(MVI69PDPMV1.Util.Finishmailboxreading) ] ,EQU(101,MVI69PDPMV1.BP.LastRead) XIC(MVI69PDPMV1.Util.Finishmailboxreading) [LES(MVI69PDPMV1.Mailbox.Class2AcyclicWrite.In.ByteCount,120) [COP(Connection_Input[2],MVI69PDPMV1.Mailbox.Class2AcyclicWrite.In.Data[88],120) ,OTU(MVI69PDPMV1.Util.FinishClass2AcyclicWrite) ,OTU(MVI69PDPMV1.Util.Finishmailboxreading) ,OTU(MVI69PDPMV1.Util.Class2AcyclicWrite101) ] ,GRT(MVI69PDPMV1.Mailbox.Class2AcyclicWrite.In.ByteCount,120) OTL(MVI69PDPMV1.Util.Finishmailboxreading) ] ,EQU(102,MVI69PDPMV1.BP.LastRead) XIC(MVI69PDPMV1.Util.Finishmailboxreading) [COP(Connection_Input[2],MVI69PDPMV1.Mailbox.Class2AcyclicWrite.In.Data[208],36) ,OTU(MVI69PDPMV1.Util.FinishClass2AcyclicWrite) ,OTU(MVI69PDPMV1.Util.Finishmailboxreading) ] ] ] ,LIM(200,MVI69PDPMV1.BP.LastRead,202) [EQU(MVI69PDPMV1.BP.LastRead,200) [MOV(Connection_Input[5],MVI69PDPMV1.Mailbox.Alarm.ByteCount) ,COP(Connection_Input[10],MVI69PDPMV1.Mailbox.Alarm.SlotNumber,2) ,COP(Connection_Input[11],MVI69PDPMV1.Mailbox.Alarm.AlarmSpecAck,2) ,COP(Connection_Input[12],MVI69PDPMV1.Mailbox.Alarm.ExtDiag,2) ,MOV(Connection_Input[17],MVI69PDPMV1.Mailbox.Alarm.FaultInformation) ,COP(Connection_Input[18],MVI69PDPMV1.Mailbox.Alarm.Data[0],88) ] ,EQU(MVI69PDPMV1.BP.LastRead,201) COP(Connection_Input[2],MVI69PDPMV1.Mailbox.Alarm.Data[88],120) ,EQU(MVI69PDPMV1.BP.LastRead,202) COP(Connection_Input[2],MVI69PDPMV1.Mailbox.Alarm.Data[208],48) ] ,EQU(Connection_Input[0],MVI69PDPMV1.BP.LastRead) [MOV(Connection_Input[1],MVI69PDPMV1.BP.LastWrite) ,XIC(MVI69PDPMV1.MailboxCommand.StopMode) [MOV(100,MVI69PDPMV1.BP.LastWrite) ,MOV(2,Connection_Output[1]) ,MOV(16386,Connection_Output[2]) ,MOV(2,Connection_Output[3]) ,MOV(0,Connection_Output[4]) ,MOV(1,Connection_Output[5]) ,MOV(1,Connection_Output[6]) ,MOV(0,Connection_Output[7]) ,MOV(0,Connection_Output[8]) ,MOV(16384,Connection_Output[9]) ] ,XIC(MVI69PDPMV1.MailboxCommand.OperateMode) [MOV(100,MVI69PDPMV1.BP.LastWrite) ,MOV(1,Connection_Output[1]) ,MOV(16386,Connection_Output[2]) ,MOV(2,Connection_Output[3]) ,MOV(0,Connection_Output[4]) ,MOV(1,Connection_Output[5]) ,MOV(1,Connection_Output[6]) ,MOV(0,Connection_Output[7]) ,MOV(0,Connection_Output[8]) ,MOV(-16384,Connection_Output[9]) ] ,XIC(MVI69PDPMV1.MailboxCommand.ClearMode) [MOV(100,MVI69PDPMV1.BP.LastWrite) ,MOV(3,Connection_Output[1]) ,MOV(16386,Connection_Output[2]) ,MOV(2,Connection_Output[3]) ,MOV(0,Connection_Output[4]) ,MOV(1,Connection_Output[5]) ,MOV(1,Connection_Output[6]) ,MOV(0,Connection_Output[7]) ,MOV(0,Connection_Output[8]) ,MOV(-32768,Connection_Output[9]) ] ,XIC(MVI69PDPMV1.MailboxCommand.GetLiveList) XIO(MVI69PDPMV1.Util.Finishgetlivelist) [MOV(100,MVI69PDPMV1.BP.LastWrite) ,MOV(4,Connection_Output[1]) ,MOV(16386,Connection_Output[2]) ,MOV(24,Connection_Output[3]) ,MOV(0,Connection_Output[4]) ,MOV(1,Connection_Output[5]) ,MOV(1,Connection_Output[6]) ,MOV(0,Connection_Output[7]) ,MOV(0,Connection_Output[8]) ,OTU(MVI69PDPMV1.MailboxCommand.GetLiveList) ,OTL(MVI69PDPMV1.Util.Finishgetlivelist) ] ,XIC(MVI69PDPMV1.MailboxCommand.GetSlaveConfig) XIO(MVI69PDPMV1.Util.FinishgetSlaveconfig) [MOV(100,MVI69PDPMV1.BP.LastWrite) ,MOV(5,Connection_Output[1]) ,MOV(16386,Connection_Output[2]) ,MOV(5,Connection_Output[3]) ,MOV(0,Connection_Output[4]) ,MOV(1,Connection_Output[5]) ,MOV(1,Connection_Output[6]) ,MOV(0,Connection_Output[7]) ,MOV(0,Connection_Output[8]) ,SWPB(MVI69PDPMV1.Mailbox.GetSlaveConfig.Out.SlaveAddress,REVERSE,MVI69PDPMV1.Util.ByteSwapUtil) ,MOV(MVI69PDPMV1.Util.ByteSwapUtil,Connection_Output[9]) ,OTU(MVI69PDPMV1.MailboxCommand.GetSlaveConfig) ,OTL(MVI69PDPMV1.Util.FinishgetSlaveconfig) ] ,XIC(MVI69PDPMV1.MailboxCommand.SetSlaveMode) [MOV(100,MVI69PDPMV1.BP.LastWrite) ,MOV(6,Connection_Output[1]) ,MOV(16386,Connection_Output[2]) ,MOV(3,Connection_Output[3]) ,MOV(0,Connection_Output[4]) ,MOV(1,Connection_Output[5]) ,MOV(1,Connection_Output[6]) ,MOV(0,Connection_Output[7]) ,MOV(0,Connection_Output[8]) ,COP(MVI69PDPMV1.Mailbox.SetSlaveMode.Out.GroupSelect,Connection_Output[9],1) ,COP(MVI69PDPMV1.Mailbox.SetSlaveMode.Out.ControlCommand,MVI69PDPMV1.Util.TempInt,1) ,SWPB(MVI69PDPMV1.Util.TempInt,REVERSE,MVI69PDPMV1.Util.ByteSwapUtil) ,MOV(MVI69PDPMV1.Util.ByteSwapUtil,Connection_Output[10]) ] ,XIC(MVI69PDPMV1.MailboxCommand.GetSlaveDiagnostics) XIO(MVI69PDPMV1.Util.FinishgetSlaveDiagnost) [MOV(100,MVI69PDPMV1.BP.LastWrite) ,MOV(7,Connection_Output[1]) ,MOV(16386,Connection_Output[2]) ,MOV(4,Connection_Output[3]) ,MOV(0,Connection_Output[4]) ,MOV(1,Connection_Output[5]) ,MOV(1,Connection_Output[6]) ,MOV(0,Connection_Output[7]) ,MOV(0,Connection_Output[8]) ,COP(MVI69PDPMV1.Mailbox.GetSlaveDiagnostics.Out.RequestType,Connection_Output[9],1) ,OTU(MVI69PDPMV1.MailboxCommand.GetSlaveDiagnostics) ,OTL(MVI69PDPMV1.Util.FinishgetSlaveDiagnost) ] ,XIC(MVI69PDPMV1.Util.SetSlaveAddress102) [MOV(102,MVI69PDPMV1.BP.LastWrite) ,COP(MVI69PDPMV1.Mailbox.SetSlaveAddress.In.MessageDataByte[208],Connection_Output[1],24) ,OTU(MVI69PDPMV1.Util.SetSlaveAddress102) ] ,XIC(MVI69PDPMV1.Util.SetSlaveAddress101) [MOV(101,MVI69PDPMV1.BP.LastWrite) ,COP(MVI69PDPMV1.Mailbox.SetSlaveAddress.In.MessageDataByte[88],Connection_Output[1],60) ,GRT(MVI69PDPMV1.Mailbox.SetSlaveAddress.Out.ByteCount,120) [OTL(MVI69PDPMV1.Util.SetSlaveAddress102) ,OTL(MVI69PDPMV1.Util.Finishmailboxreading) ] ,OTU(MVI69PDPMV1.Util.SetSlaveAddress101) ] ,XIC(MVI69PDPMV1.MailboxCommand.SetSlaveAddress) XIO(MVI69PDPMV1.Util.FinishSetSlaveAddr) [MOV(100,MVI69PDPMV1.BP.LastWrite) ,MOV(8,Connection_Output[1]) ,MOV(16386,Connection_Output[2]) ,MOV(6,Connection_Output[3]) ,MOV(MVI69PDPMV1.Mailbox.SetSlaveAddress.Out.ByteCount,Connection_Output[4]) ,MOV(1,Connection_Output[5]) ,MOV(1,Connection_Output[6]) ,MOV(0,Connection_Output[7]) ,MOV(0,Connection_Output[8]) ,COP(MVI69PDPMV1.Mailbox.SetSlaveAddress.Out.NewSlaveAddress,Connection_Output[9],1) ,MOV(MVI69PDPMV1.Mailbox.SetSlaveAddress.Out.SlaveIdentNumber,Connection_Output[10]) ,SWPB(MVI69PDPMV1.Mailbox.SetSlaveAddress.Out.No_add_Chg,REVERSE,MVI69PDPMV1.Util.ByteSwapUtil) ,MOV(MVI69PDPMV1.Util.ByteSwapUtil,Connection_Output[11]) ,COP(MVI69PDPMV1.Mailbox.SetSlaveAddress.Out.MessageDataByte[0],Connection_Output[17],42) ,OTU(MVI69PDPMV1.MailboxCommand.SetSlaveAddress) ,OTL(MVI69PDPMV1.Util.FinishSetSlaveAddr) ] ,XIC(MVI69PDPMV1.Util.FinishStartStopSlaves) EQU(MVI69PDPMV1.BP.LastWrite,101) [MOV(101,MVI69PDPMV1.BP.LastWrite) ,COP(MVI69PDPMV1.Mailbox.StartStopSlaves.Out.SlaveNumber[88],Connection_Output[1],19) ] ,XIC(MVI69PDPMV1.MailboxCommand.StartSlaves) XIO(MVI69PDPMV1.Util.FinishStartStopSlaves) [MOV(100,MVI69PDPMV1.BP.LastWrite) ,MOV(16,Connection_Output[1]) ,MOV(16386,Connection_Output[2]) ,MOV(11,Connection_Output[3]) ,MOV(126,Connection_Output[4]) ,MOV(1,Connection_Output[5]) ,MOV(1,Connection_Output[6]) ,MOV(0,Connection_Output[7]) ,MOV(0,Connection_Output[8]) ,MOV(0,Connection_Output[9]) ,MOV(0,Connection_Output[10]) ,MOV(0,Connection_Output[11]) ,MOV(0,Connection_Output[12]) ,MOV(0,Connection_Output[13]) ,MOV(0,Connection_Output[14]) ,MOV(0,Connection_Output[15]) ,MOV(0,Connection_Output[16]) ,COP(MVI69PDPMV1.Mailbox.StartStopSlaves.Out.SlaveNumber[0],Connection_Output[17],44) ,OTU(MVI69PDPMV1.MailboxCommand.StartSlaves) ,OTL(MVI69PDPMV1.Util.FinishStartStopSlaves) ] ,XIC(MVI69PDPMV1.MailboxCommand.StopSlaves) XIO(MVI69PDPMV1.Util.FinishStartStopSlaves) [MOV(100,MVI69PDPMV1.BP.LastWrite) ,MOV(17,Connection_Output[1]) ,MOV(16386,Connection_Output[2]) ,MOV(12,Connection_Output[3]) ,MOV(126,Connection_Output[4]) ,MOV(1,Connection_Output[5]) ,MOV(1,Connection_Output[6]) ,MOV(0,Connection_Output[7]) ,MOV(0,Connection_Output[8]) ,MOV(0,Connection_Output[9]) ,MOV(0,Connection_Output[10]) ,MOV(0,Connection_Output[11]) ,MOV(0,Connection_Output[12]) ,MOV(0,Connection_Output[13]) ,MOV(0,Connection_Output[14]) ,MOV(0,Connection_Output[15]) ,MOV(0,Connection_Output[16]) ,COP(MVI69PDPMV1.Mailbox.StartStopSlaves.Out.SlaveNumber[0],Connection_Output[17],44) ,OTU(MVI69PDPMV1.MailboxCommand.StopSlaves) ,OTL(MVI69PDPMV1.Util.FinishStartStopSlaves) ] ,XIC(MVI69PDPMV1.MailboxCommand.Class1AcyclicRead) XIO(MVI69PDPMV1.Util.FinishClass1AcyclicRead) [MOV(100,MVI69PDPMV1.BP.LastWrite) ,MOV(9,Connection_Output[1]) ,MOV(16386,Connection_Output[2]) ,MOV(32,Connection_Output[3]) ,COP(MVI69PDPMV1.Mailbox.Class1AcyclicRead.Out.DataSize,MVI69PDPMV1.Mailbox.Class1AcyclicRead.Out.Length,1) ,MOV(0,Connection_Output[4]) ,MOV(1,Connection_Output[5]) ,MOV(1,Connection_Output[6]) ,MOV(0,Connection_Output[7]) ,MOV(0,Connection_Output[8]) ,COP(MVI69PDPMV1.Mailbox.Class1AcyclicRead.Out.SlotNumber,Connection_Output[9],1) ,COP(MVI69PDPMV1.Mailbox.Class1AcyclicRead.Out.Length,Connection_Output[10],1) ,OTU(MVI69PDPMV1.MailboxCommand.Class1AcyclicRead) ,OTL(MVI69PDPMV1.Util.FinishClass1AcyclicRead) ] ,XIC(MVI69PDPMV1.Util.Class1AcyclicWrite102) [MOV(102,MVI69PDPMV1.BP.LastWrite) ,COP(MVI69PDPMV1.Mailbox.Class1AcyclicWrite.Out.Data[208],Connection_Output[1],24) ,OTU(MVI69PDPMV1.Util.Class1AcyclicWrite102) ] ,XIC(MVI69PDPMV1.Util.Class1AcyclicWrite101) [MOV(101,MVI69PDPMV1.BP.LastWrite) ,COP(MVI69PDPMV1.Mailbox.Class1AcyclicWrite.Out.Data[88],Connection_Output[1],60) ,GRT(MVI69PDPMV1.Util.TempInt2,120) OTL(MVI69PDPMV1.Util.Class1AcyclicWrite102) ,OTU(MVI69PDPMV1.Util.Class1AcyclicWrite101) ] ,XIC(MVI69PDPMV1.MailboxCommand.Class1AcyclicWrite) XIO(MVI69PDPMV1.Util.FinishClass1AcyclicWrite) [MOV(100,MVI69PDPMV1.BP.LastWrite) ,MOV(10,Connection_Output[1]) ,MOV(16386,Connection_Output[2]) ,MOV(33,Connection_Output[3]) ,COP(MVI69PDPMV1.Mailbox.Class1AcyclicWrite.Out.DataSize,MVI69PDPMV1.Mailbox.Class1AcyclicWrite.Out.Length,1) ,COP(MVI69PDPMV1.Mailbox.Class1AcyclicWrite.Out.DataSize,MVI69PDPMV1.Util.TempInt2,1) ,MOV(MVI69PDPMV1.Mailbox.Class1AcyclicWrite.Out.DataSize,Connection_Output[4]) ,MOV(1,Connection_Output[5]) ,MOV(1,Connection_Output[6]) ,MOV(0,Connection_Output[7]) ,MOV(0,Connection_Output[8]) ,COP(MVI69PDPMV1.Mailbox.Class1AcyclicWrite.Out.SlotNumber,Connection_Output[9],1) ,COP(MVI69PDPMV1.Mailbox.Class1AcyclicWrite.Out.Length,Connection_Output[10],1) ,COP(MVI69PDPMV1.Mailbox.Class1AcyclicWrite.Out.Data[0],Connection_Output[17],44) ,GRT(MVI69PDPMV1.Util.TempInt2,88) [SUB(MVI69PDPMV1.Util.TempInt2,88,MVI69PDPMV1.Util.TempInt2) ,OTL(MVI69PDPMV1.Util.Class1AcyclicWrite101) ] ,OTL(MVI69PDPMV1.Util.FinishClass1AcyclicWrite) ,OTU(MVI69PDPMV1.MailboxCommand.Class1AcyclicWrite) ] ,XIC(MVI69PDPMV1.MailboxCommand.InitiateConnection) [MOV(100,MVI69PDPMV1.BP.LastWrite) ,MOV(11,Connection_Output[1]) ,MOV(16386,Connection_Output[2]) ,MOV(37,Connection_Output[3]) ,MOV(0,Connection_Output[4]) ,MOV(1,Connection_Output[5]) ,MOV(1,Connection_Output[6]) ,MOV(0,Connection_Output[7]) ,MOV(0,Connection_Output[8]) ,MOV(MVI69PDPMV1.Mailbox.InitiateConnection.Out.C_REF,Connection_Output[9]) ,SWPB(MVI69PDPMV1.Mailbox.InitiateConnection.Out.SlaveAddress,REVERSE,MVI69PDPMV1.Util.ByteSwapUtil) ,MOV(MVI69PDPMV1.Util.ByteSwapUtil,Connection_Output[10]) ,OTU(MVI69PDPMV1.MailboxCommand.InitiateConnection) ] ,XIC(MVI69PDPMV1.MailboxCommand.AbortConnection) [MOV(100,MVI69PDPMV1.BP.LastWrite) ,MOV(12,Connection_Output[1]) ,MOV(16386,Connection_Output[2]) ,MOV(38,Connection_Output[3]) ,MOV(0,Connection_Output[4]) ,MOV(1,Connection_Output[5]) ,MOV(1,Connection_Output[6]) ,MOV(0,Connection_Output[7]) ,MOV(0,Connection_Output[8]) ,MOV(MVI69PDPMV1.Mailbox.AbortConnection.Out.C_REF,Connection_Output[9]) ,COP(MVI69PDPMV1.Mailbox.AbortConnection.Out.ReasonCode,Connection_Output[10],1) ,OTU(MVI69PDPMV1.MailboxCommand.AbortConnection) ] ,XIC(MVI69PDPMV1.MailboxCommand.Class2AcyclicRead) XIO(MVI69PDPMV1.Util.FinishClass2AcyclicRead) [MOV(100,MVI69PDPMV1.BP.LastWrite) ,MOV(9,Connection_Output[1]) ,MOV(16386,Connection_Output[2]) ,MOV(39,Connection_Output[3]) ,MOV(0,Connection_Output[4]) ,MOV(1,Connection_Output[5]) ,MOV(1,Connection_Output[6]) ,MOV(0,Connection_Output[7]) ,MOV(0,Connection_Output[8]) ,MOV(MVI69PDPMV1.Mailbox.Class2AcyclicRead.Out.C_REF,Connection_Output[9]) ,COP(MVI69PDPMV1.Mailbox.Class2AcyclicRead.Out.Index,Connection_Output[10],1) ,SWPB(MVI69PDPMV1.Mailbox.Class2AcyclicRead.Out.Length,REVERSE,MVI69PDPMV1.Util.ByteSwapUtil) ,MOV(MVI69PDPMV1.Util.ByteSwapUtil,Connection_Output[11]) ,OTU(MVI69PDPMV1.MailboxCommand.Class2AcyclicRead) ,OTL(MVI69PDPMV1.Util.FinishClass2AcyclicRead) ] ,XIC(MVI69PDPMV1.Util.Class2AcyclicWrite102) [MOV(102,MVI69PDPMV1.BP.LastWrite) ,COP(MVI69PDPMV1.Mailbox.Class2AcyclicWrite.Out.Data[208],Connection_Output[1],24) ,OTU(MVI69PDPMV1.Util.Class2AcyclicWrite102) ] ,XIC(MVI69PDPMV1.Util.Class2AcyclicWrite101) [MOV(101,MVI69PDPMV1.BP.LastWrite) ,COP(MVI69PDPMV1.Mailbox.Class2AcyclicWrite.Out.Data[88],Connection_Output[1],60) ,GRT(MVI69PDPMV1.Util.TempInt2,120) OTL(MVI69PDPMV1.Util.Class2AcyclicWrite102) ,OTU(MVI69PDPMV1.Util.Class2AcyclicWrite101) ] ,XIC(MVI69PDPMV1.MailboxCommand.Class2AcyclicWrite) XIO(MVI69PDPMV1.Util.FinishClass2AcyclicWrite) [MOV(100,MVI69PDPMV1.BP.LastWrite) ,MOV(10,Connection_Output[1]) ,MOV(16386,Connection_Output[2]) ,MOV(40,Connection_Output[3]) ,COP(MVI69PDPMV1.Mailbox.Class2AcyclicWrite.Out.DataSize,MVI69PDPMV1.Mailbox.Class2AcyclicWrite.Out.Length,1) ,COP(MVI69PDPMV1.Mailbox.Class2AcyclicWrite.Out.DataSize,MVI69PDPMV1.Util.TempInt2,1) ,MOV(MVI69PDPMV1.Mailbox.Class2AcyclicWrite.Out.DataSize,Connection_Output[4]) ,MOV(1,Connection_Output[5]) ,MOV(1,Connection_Output[6]) ,MOV(0,Connection_Output[7]) ,MOV(0,Connection_Output[8]) ,MOV(MVI69PDPMV1.Mailbox.Class2AcyclicWrite.Out.C_REF,Connection_Output[9]) ,COP(MVI69PDPMV1.Mailbox.Class2AcyclicWrite.Out.Index,Connection_Output[10],1) ,SWPB(MVI69PDPMV1.Mailbox.Class2AcyclicWrite.Out.Length,REVERSE,MVI69PDPMV1.Util.ByteSwapUtil) ,MOV(MVI69PDPMV1.Util.ByteSwapUtil,Connection_Output[11]) ,COP(MVI69PDPMV1.Mailbox.Class2AcyclicWrite.Out.Data[0],Connection_Output[17],44) ,GRT(MVI69PDPMV1.Util.TempInt2,88) [SUB(MVI69PDPMV1.Util.TempInt2,88,MVI69PDPMV1.Util.TempInt2) ,OTL(MVI69PDPMV1.Util.Class2AcyclicWrite101) ] ,OTL(MVI69PDPMV1.Util.FinishClass2AcyclicWrite) ,OTU(MVI69PDPMV1.MailboxCommand.Class2AcyclicWrite) ] ,XIC(MVI69PDPMV1.MailboxCommand.SynchCRC) [MOV(MVI69PDPMV1.CRC.In.ProfibusCRC,MVI69PDPMV1.CRC.Out.ProfibusCRC) ,MOV(MVI69PDPMV1.CRC.In.ModuleCRC,MVI69PDPMV1.CRC.Out.ModuleCRC) ,OTU(MVI69PDPMV1.MailboxCommand.SynchCRC) ] ] ,LIM(1,MVI69PDPMV1.BP.LastWrite,16) [CPT(MVI69PDPMV1.BP.BlockIndex,(MVI69PDPMV1.BP.LastWrite-1)*100) ,LIM(1,MVI69PDPMV1.BP.LastWrite,15) COP(MVI69PDPMV1.Output[MVI69PDPMV1.BP.BlockIndex],Connection_Output[1],50) ,EQU(MVI69PDPMV1.BP.LastWrite,16) COP(MVI69PDPMV1.Output[1500],Connection_Output[1],36) ,COP(MVI69PDPMV1.MailboxControl.Out_Last_Out_MB,Connection_Output[51],2) ,COP(MVI69PDPMV1.CRC.Out.ProfibusCRC,Connection_Output[54],4) ] ,MOV(MVI69PDPMV1.BP.LastWrite,Connection_Output[0]) ];
END_ROUTINE
END_ADD_ON_INSTRUCTION

VAR_GLOBAL   (* controller tags *)
   AOI69PDPMV1_60 : AOI69PDPMV1_60;
   MVI69PDPMV1 : PDPMV1_ModuleDef;
END_VAR

PROGRAM MainProgram   (* main routine MainRoutine *)

ROUTINE MainRoutine   (* ladder *)
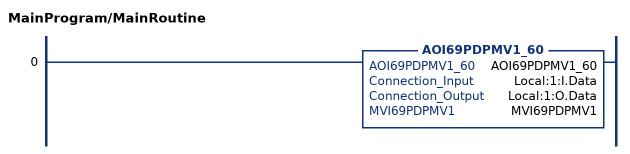
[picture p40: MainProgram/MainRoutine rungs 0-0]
   0: AOI69PDPMV1_60(AOI69PDPMV1_60,Local:1:I.Data,Local:1:O.Data,MVI69PDPMV1);
END_ROUTINE
END_PROGRAM
